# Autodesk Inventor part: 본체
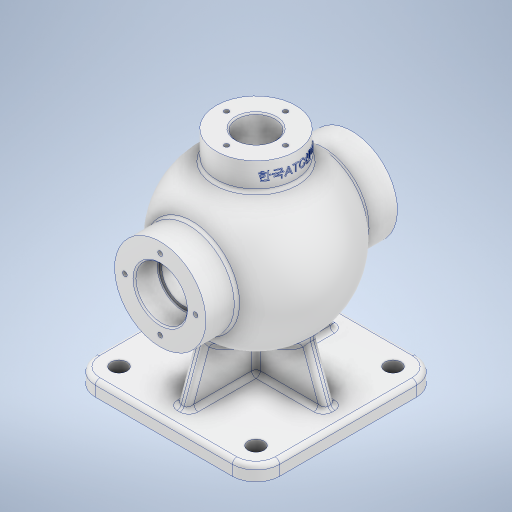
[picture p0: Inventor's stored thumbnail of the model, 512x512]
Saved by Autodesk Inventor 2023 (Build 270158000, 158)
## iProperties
Created: 2023-07
Part Number: 본체
Material: 알루미늄 6061
Document SubType Name: Modeling
Designer: Owner
Density: 2.7 g/cm^3
Appearance: 알루미늄 - 평지
Mass: 1526.72 g
Surface Area: 1173.82 cm^2
Volume: 565.453 cm^3
Author: Owner
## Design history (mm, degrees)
sketch "스케치1"
  geometry: L1 (62.5, 62.5)-(-62.5, 62.5); L2 (-62.5, 62.5)-(-62.5, -62.5); L3 (-62.5, -62.5)-(62.5, -62.5); L4 (62.5, -62.5)-(62.5, 62.5); L5 (62.5, 62.5)-(-62.5, -62.5); L6 (-62.5, 62.5)-(62.5, -62.5); 1 further point
  constraints: 12 end point, 2 midpoint, 2 parallel, 1 horizontal, 1 perpendicular
  dimensions: "d0" = 125 distance of L2.end L3.end; "d1" = 125 distance of L1.end L2.end
extrude "돌출1" new body sketch "스케치1" distance "d2" = 10; taper "d3" = 0 deg
sketch "스케치2"
  geometry: L1 (0, -62.5)-(0, 62.5) reference; L2 (85, 65)-(85, -65); L3 (85, 65)-(54, 65); L4 (54, -65)-(85, -65); L5 (54, 65)-(54, 44.215); L6 (54, -44.215)-(54, -65); A1 r 54 centre (85, 0) between (54, 44.215) and (54, -44.215); 2 further points
  constraints: 10 end point, 4 perpendicular, 2 midpoint, 2 point on circle, 1 centre point, 1 horizontal, 1 horizontal alignment, 1 vertical, 1 vertical alignment
  dimensions: "d6" = 130 distance of L2.start L2.end; "d7" = 85 distance between parallel lines of L1 L2; "d8" = 54 radius of A1; "d9" = 31 distance between parallel lines of L6 L2
revolve "회전1" sketch "스케치2" stored, may be unused: angle "d10" = 90 deg
sketch "스케치3"
  geometry: L1 (0, -62.5)-(0, 62.5) reference; L2 (0, 62.5)-(10, 62.5) reference; L3 (10, -62.5)-(10, 62.5) reference; L4 (0, -62.5)-(10, -62.5) reference; L5 (10, 50.5)-(85, 23.202); L6 (85, 23.202)-(85, -23.202); L7 (85, -23.202)-(10, -50.5); 1 further point
  constraints: 6 end point, 2 point on line, 1 vertical
  dimensions: "d11" = 12 distance from line of L4 L7.end; "d12" = 12 distance of L2.end L5.start; "d13" = 20 deg angle of L4 L7; "d14" = 20 deg angle of L2 L5; "d15" = 85 distance between parallel lines of L1 L6
extrude "돌출2" join sketch "스케치3" stored distance "d16" = 8; taper "d17" = 0 deg
sketch "스케치4"
  geometry: L1 (62.5, 10)-(-62.5, 10) reference; L2 (50.5, 10)-(42.822, 31.095); L3 (62.5, 0)-(62.5, 10) reference; 1 further point
  constraints: 2 end point, 1 point on line
  dimensions: "d18" = 12 distance from line of L3 L2.start; "d19" = 20 deg angle of L3 L2
feature "리브1" sketch "스케치4" dims "d20" = 1, "d21" = 8, "d22" = 0, "d23" = 0, "d24" = 1, "d25" = 1
sketch "스케치6"
  geometry: L1 (85, 44)-(85, -44); A1 r 54 centre (85, 0) between (46.034, -37.385) and (46.034, 37.385) reference; A2 r 44 centre (85, 0) between (85, -44) and (85, 44); 2 further points
  constraints: 2 coincident, 2 end point, 2 point on circle, 1 centre point, 1 midpoint, 1 vertical
  dimensions: "d26" = 88 diameter of A2
revolve "회전2" sketch "스케치6" stored, may be unused: angle "d27" = 90 deg
sketch "스케치7"
  geometry: C1 r 31 at (0, 0) reference; 2 further points
  constraints: 1 coincident
hole "구멍1" sketch "스케치7" at (0, 0) diameter "d28" = 30; stored, may be unused: countersink angle "d32" = 90 deg, drill point angle "d34" = 118 deg; dims "d29" = 6, "d30" = 35, "d31" = 16, "d33" = 8
sketch "스케치8"
  geometry: C1 r 31 at (0, 0) reference; 2 further points
  constraints: 1 coincident
hole "구멍2" sketch "스케치8" at (0, 0) diameter "d35" = 30; stored, may be unused: countersink angle "d39" = 90 deg, drill point angle "d41" = 118 deg; dims "d36" = 6, "d37" = 35, "d38" = 16, "d40" = 8
node "작업 평면1"
sketch "스케치9"
  geometry: C1 r 27 at (0, 0); 1 further point
  constraints: 1 centre point, 1 coincident
  dimensions: "d43" = 54 diameter of C1
extrude "돌출3" join sketch "스케치9" stored distance "d44" = 8; taper "d45" = 0 deg
sketch "스케치10"
  geometry: C1 r 27 at (0, 0) reference; 2 further points
  constraints: 1 coincident
hole "구멍3" sketch "스케치10" at (0, 0) diameter "d46" = 26; stored, may be unused: countersink angle "d50" = 90 deg, drill point angle "d52" = 118 deg; dims "d47" = 6, "d48" = 35, "d49" = 16, "d51" = 8
sketch "스케치11"
  geometry: C1 r 17.5 at (0, 0) reference; 2 further points
  constraints: 1 vertical alignment
  dimensions: "d53" = 24 distance of C1.centre point (0, 24)
hole "구멍4" sketch "스케치11" at (0, 24) diameter "d54" = 3.242; stored, may be unused: countersink angle "d58" = 90 deg, drill point angle "d60" = 118 deg; dims "d55" = 12, "d56" = 4, "d57" = 2, "d59" = 15
sketch "스케치12"
  geometry: C1 r 13 at (0, 0) reference; 1 further point
  constraints: 1 vertical alignment
  dimensions: "d64" = 20 distance of point (0, 20) C1.centre
hole "구멍5" sketch "스케치12" at (0, 20) diameter "d65" = 3.242; stored, may be unused: countersink angle "d69" = 90 deg, drill point angle "d71" = 118 deg; dims "d66" = 9, "d67" = 4, "d68" = 2, "d70" = 11
fillet "모깎기1" dims "d75" = 16
sketch "스케치13"
  geometry: A1 r 16 centre (46.5, -46.5) between (46.5, -62.5) and (62.5, -46.5) reference; 2 further points
  constraints: 1 coincident
hole "구멍6" sketch "스케치13" at (46.5, -46.5) diameter "d76" = 11; stored, may be unused: countersink angle "d80" = 90 deg, drill point angle "d82" = 118 deg; dims "d77" = 9, "d78" = 4, "d79" = 2, "d81" = 11
fillet "모깎기2" dims "d83" = 3
fillet "모깎기3" dims "d84" = 3
fillet "모깎기4" dims "d85" = 0.6
chamfer "모따기1" distance "d86" = 1; stored, may be unused: second distance "d87" = 2, angle "d88" = 45 deg
node "작업 평면2"
sketch "스케치14"
  geometry: L1 (150, -27)-(150, 27) reference; 2 further points
  constraints: 1 horizontal alignment, 1 other
  dimensions: "d90" = 9 distance from line of point (141, 0) L1
feature "엠보싱1" sketch "스케치14" dims "d0" = 125, "d1" = 125, "d91" = 0.5, "d92" = 0
feature "̵耀̷耀̹耀̻耀̽耀̿耀́耀̓耀" dims "d0" = 125, "d1" = 125, "d2" = 10, "d3" = 0, "d6" = 130, "d7" = 85, "d8" = 54, "d9" = 31, "d10" = 90 deg, "d11" = 12, "d12" = 12, "d13" = 20 deg, "d14" = 20 deg, "d15" = 85, "d16" = 8, "d17" = 0, "d18" = 12, "d19" = 20 deg, "d20" = 1, "d21" = 8, "d22" = 0, "d23" = 0, "d24" = 1, "d25" = 1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
node "솔리드1"
mirror "미러1"
pattern_circular "원형 패턴1" dims angle "d62" = 360 deg
mirror "미러2"
pattern_circular "원형 패턴2" dims angle "d73" = 360 deg
mirror "미러3"
mirror "미러4"
node "투영된 루프1"
feature "A9D066F2-1C7D-4E18-AEED-F7BC21143FA4" dims "d28" = 30, "d29" = 6, "d30" = 35, "d31" = 16, "d32" = 90 deg, "d33" = 8, "d34" = 118 deg
